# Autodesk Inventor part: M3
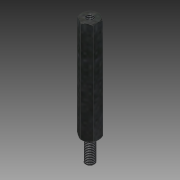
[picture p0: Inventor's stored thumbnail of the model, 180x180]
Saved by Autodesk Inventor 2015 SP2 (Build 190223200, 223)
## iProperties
Created: 2012-08
Part Number: M3
Material: Stahl
Document SubType Name: Modeling
Designer: rYan
Density: 7.85 g/cm^3
Mass: 1.74537 g
Surface Area: 3.04272 cm^2
Volume: 0.22234 cm^3
Appearance: Platte
Author: rYan
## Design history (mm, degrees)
derived "Abstandsbolzen Typ B.ipt"
feature "Volumenkörper1::Abstandsbolzen Typ B.ipt"
tag "Bezeichnung1"
node "Volumenkörper1"
other parameters: "SW" = 5.5, "L" = 35, "d2" = 0, "d9" = 118 deg, "GA_" = 3, "A_" = 8, "d13" = 0, "d17" = 0.25, "d20" = 45 deg
